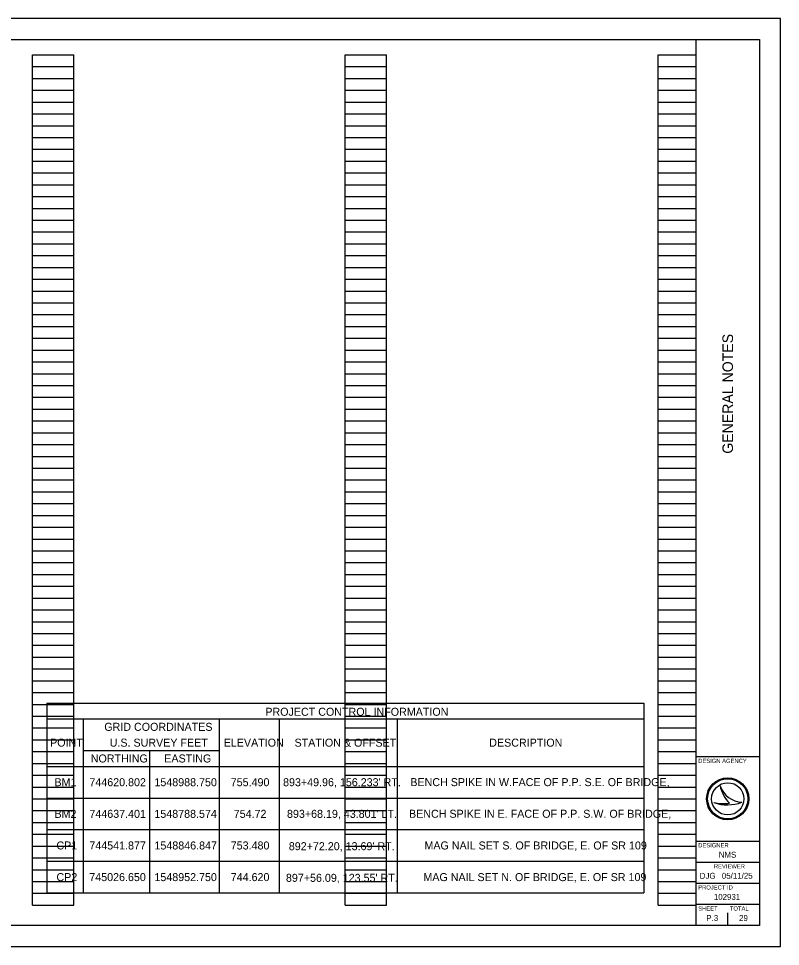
# Model space of a CAD drawing. Extents: x 0 to 34, y 0 to 22.
# Drawn here: x 15.93 to 34, y 0 to 22 of the extents above; entities that cross this region are included whole.
import ezdxf

# ---------------------------------------------------------------- set-up
doc = ezdxf.new("R2010")
doc.units = 0
for name, color, linetype in [('Default', 7, 'Continuous'), ('SH_Border', 7, 'Continuous'), ('SH_Cut_Line', 7, 'Continuous'), ('SH_Data', 7, 'Continuous'), ('SH_Text', 7, 'Continuous')]:
    doc.layers.add(name, color=color, linetype=linetype)

msp = doc.modelspace()

# ---------------------------------------------------------------- linework, layer by layer
at = {"layer": 'Default'}
for p, q in [((16.602, 5.769), (30.758, 5.769)), ((16.602, 5.769), (16.602, 1.269)), ((30.758, 5.769), (30.758, 1.269)), ((16.602, 5.394), (30.758, 5.394)), ((17.464, 5.394), (17.464, 1.269)), ((20.689, 5.394), (20.689, 1.269)), ((22.114, 5.394), (22.114, 1.269)), ((24.908, 5.394), (24.908, 1.269)), ((17.464, 4.644), (20.689, 4.644)), ((19.039, 4.644), (19.039, 1.269)), ((16.602, 4.269), (30.758, 4.269)), ((16.602, 3.519), (30.758, 3.519)), ((16.602, 2.769), (30.758, 2.769)), ((16.602, 2.019), (30.758, 2.019)), ((16.602, 1.269), (30.758, 1.269)), ((16.602, 1.269), (30.758, 1.269))]:
    msp.add_line(p, q, dxfattribs=at)
at = {"layer": 'SH_Border'}
for p, q in [((32, 0.5), (32, 21.5)), ((32, 4.5), (33.5, 4.5)), ((32, 2.5), (33.5, 2.5)), ((32, 2), (33.5, 2)), ((32, 1.5), (33.5, 1.5)), ((32, 1), (33.5, 1))]:
    msp.add_line(p, q, dxfattribs=at)
msp.add_lwpolyline([(1.5, 21.5), (33.5, 21.5), (33.5, 0.5), (1.5, 0.5)], close=True, dxfattribs=at)
at = {"layer": 'SH_Cut_Line'}
msp.add_lwpolyline([(0, 0), (34, 0), (34, 22), (0, 22)], close=True, dxfattribs=at)
at = {"layer": 'SH_Data'}
for p, q in [((16.26, 0.98), (16.26, 21.14)), ((16.26, 21.14), (17.24, 21.14)), ((17.24, 0.98), (17.24, 21.14)), ((23.68, 0.98), (23.68, 21.14)), ((23.68, 21.14), (24.66, 21.14)), ((24.66, 0.98), (24.66, 21.14)), ((31.1, 0.98), (31.1, 21.14)), ((31.1, 21.14), (32, 21.14)), ((32, 0.98), (32, 21.14)), ((16.26, 20.86), (17.24, 20.86)), ((23.68, 20.86), (24.66, 20.86)), ((31.1, 20.86), (32, 20.86)), ((16.26, 20.58), (17.24, 20.58)), ((23.68, 20.58), (24.66, 20.58)), ((31.1, 20.58), (32, 20.58)), ((16.26, 20.3), (17.24, 20.3)), ((23.68, 20.3), (24.66, 20.3)), ((31.1, 20.3), (32, 20.3)), ((16.26, 20.02), (17.24, 20.02)), ((23.68, 20.02), (24.66, 20.02)), ((31.1, 20.02), (32, 20.02)), ((16.26, 19.74), (17.24, 19.74)), ((23.68, 19.74), (24.66, 19.74)), ((31.1, 19.74), (32, 19.74)), ((16.26, 19.46), (17.24, 19.46)), ((23.68, 19.46), (24.66, 19.46)), ((31.1, 19.46), (32, 19.46)), ((16.26, 19.18), (17.24, 19.18)), ((23.68, 19.18), (24.66, 19.18)), ((31.1, 19.18), (32, 19.18)), ((16.26, 18.9), (17.24, 18.9)), ((23.68, 18.9), (24.66, 18.9)), ((31.1, 18.9), (32, 18.9)), ((16.26, 18.62), (17.24, 18.62)), ((23.68, 18.62), (24.66, 18.62)), ((31.1, 18.62), (32, 18.62)), ((16.26, 18.34), (17.24, 18.34)), ((23.68, 18.34), (24.66, 18.34)), ((31.1, 18.34), (32, 18.34)), ((16.26, 18.06), (17.24, 18.06)), ((23.68, 18.06), (24.66, 18.06)), ((31.1, 18.06), (32, 18.06)), ((16.26, 17.78), (17.24, 17.78)), ((23.68, 17.78), (24.66, 17.78)), ((31.1, 17.78), (32, 17.78)), ((16.26, 17.5), (17.24, 17.5)), ((23.68, 17.5), (24.66, 17.5)), ((31.1, 17.5), (32, 17.5)), ((16.26, 17.22), (17.24, 17.22)), ((23.68, 17.22), (24.66, 17.22)), ((31.1, 17.22), (32, 17.22)), ((16.26, 16.94), (17.24, 16.94)), ((23.68, 16.94), (24.66, 16.94)), ((31.1, 16.94), (32, 16.94)), ((16.26, 16.66), (17.24, 16.66)), ((23.68, 16.66), (24.66, 16.66)), ((31.1, 16.66), (32, 16.66)), ((16.26, 16.38), (17.24, 16.38)), ((23.68, 16.38), (24.66, 16.38)), ((31.1, 16.38), (32, 16.38)), ((16.26, 16.1), (17.24, 16.1)), ((23.68, 16.1), (24.66, 16.1)), ((31.1, 16.1), (32, 16.1)), ((16.26, 15.82), (17.24, 15.82)), ((23.68, 15.82), (24.66, 15.82)), ((31.1, 15.82), (32, 15.82)), ((16.26, 15.54), (17.24, 15.54)), ((23.68, 15.54), (24.66, 15.54)), ((31.1, 15.54), (32, 15.54)), ((16.26, 15.26), (17.24, 15.26)), ((23.68, 15.26), (24.66, 15.26)), ((31.1, 15.26), (32, 15.26)), ((16.26, 14.98), (17.24, 14.98)), ((23.68, 14.98), (24.66, 14.98)), ((31.1, 14.98), (32, 14.98)), ((16.26, 14.7), (17.24, 14.7)), ((23.68, 14.7), (24.66, 14.7)), ((31.1, 14.7), (32, 14.7)), ((16.26, 14.42), (17.24, 14.42)), ((23.68, 14.42), (24.66, 14.42)), ((31.1, 14.42), (32, 14.42)), ((16.26, 14.14), (17.24, 14.14)), ((23.68, 14.14), (24.66, 14.14)), ((31.1, 14.14), (32, 14.14)), ((16.26, 13.86), (17.24, 13.86)), ((23.68, 13.86), (24.66, 13.86)), ((31.1, 13.86), (32, 13.86)), ((16.26, 13.58), (17.24, 13.58)), ((23.68, 13.58), (24.66, 13.58)), ((31.1, 13.58), (32, 13.58)), ((16.26, 13.3), (17.24, 13.3)), ((23.68, 13.3), (24.66, 13.3)), ((31.1, 13.3), (32, 13.3)), ((16.26, 13.02), (17.24, 13.02)), ((23.68, 13.02), (24.66, 13.02)), ((31.1, 13.02), (32, 13.02)), ((16.26, 12.74), (17.24, 12.74)), ((23.68, 12.74), (24.66, 12.74)), ((31.1, 12.74), (32, 12.74)), ((16.26, 12.46), (17.24, 12.46)), ((23.68, 12.46), (24.66, 12.46)), ((31.1, 12.46), (32, 12.46)), ((16.26, 12.18), (17.24, 12.18)), ((23.68, 12.18), (24.66, 12.18)), ((31.1, 12.18), (32, 12.18)), ((16.26, 11.9), (17.24, 11.9)), ((23.68, 11.9), (24.66, 11.9)), ((31.1, 11.9), (32, 11.9)), ((16.26, 11.62), (17.24, 11.62)), ((23.68, 11.62), (24.66, 11.62)), ((31.1, 11.62), (32, 11.62)), ((16.26, 11.34), (17.24, 11.34)), ((23.68, 11.34), (24.66, 11.34)), ((31.1, 11.34), (32, 11.34)), ((16.26, 11.06), (17.24, 11.06)), ((23.68, 11.06), (24.66, 11.06)), ((31.1, 11.06), (32, 11.06)), ((16.26, 10.78), (17.24, 10.78)), ((23.68, 10.78), (24.66, 10.78)), ((31.1, 10.78), (32, 10.78)), ((16.26, 10.5), (17.24, 10.5)), ((23.68, 10.5), (24.66, 10.5)), ((31.1, 10.5), (32, 10.5)), ((16.26, 10.22), (17.24, 10.22)), ((23.68, 10.22), (24.66, 10.22)), ((31.1, 10.22), (32, 10.22)), ((16.26, 9.94), (17.24, 9.94)), ((23.68, 9.94), (24.66, 9.94)), ((31.1, 9.94), (32, 9.94)), ((16.26, 9.66), (17.24, 9.66)), ((23.68, 9.66), (24.66, 9.66)), ((31.1, 9.66), (32, 9.66)), ((16.26, 9.38), (17.24, 9.38)), ((23.68, 9.38), (24.66, 9.38)), ((31.1, 9.38), (32, 9.38)), ((16.26, 9.1), (17.24, 9.1)), ((23.68, 9.1), (24.66, 9.1)), ((31.1, 9.1), (32, 9.1)), ((16.26, 8.82), (17.24, 8.82)), ((23.68, 8.82), (24.66, 8.82)), ((31.1, 8.82), (32, 8.82)), ((16.26, 8.54), (17.24, 8.54)), ((23.68, 8.54), (24.66, 8.54)), ((31.1, 8.54), (32, 8.54)), ((16.26, 8.26), (17.24, 8.26)), ((23.68, 8.26), (24.66, 8.26)), ((31.1, 8.26), (32, 8.26)), ((16.26, 7.98), (17.24, 7.98)), ((23.68, 7.98), (24.66, 7.98)), ((31.1, 7.98), (32, 7.98)), ((16.26, 7.7), (17.24, 7.7)), ((23.68, 7.7), (24.66, 7.7)), ((31.1, 7.7), (32, 7.7)), ((16.26, 7.42), (17.24, 7.42)), ((23.68, 7.42), (24.66, 7.42)), ((31.1, 7.42), (32, 7.42)), ((16.26, 7.14), (17.24, 7.14)), ((23.68, 7.14), (24.66, 7.14)), ((31.1, 7.14), (32, 7.14)), ((16.26, 6.86), (17.24, 6.86)), ((23.68, 6.86), (24.66, 6.86)), ((31.1, 6.86), (32, 6.86)), ((16.26, 6.58), (17.24, 6.58)), ((23.68, 6.58), (24.66, 6.58)), ((31.1, 6.58), (32, 6.58)), ((16.26, 6.3), (17.24, 6.3)), ((23.68, 6.3), (24.66, 6.3)), ((31.1, 6.3), (32, 6.3)), ((16.26, 6.02), (17.24, 6.02)), ((23.68, 6.02), (24.66, 6.02)), ((31.1, 6.02), (32, 6.02)), ((16.26, 5.74), (17.24, 5.74)), ((23.68, 5.74), (24.66, 5.74)), ((31.1, 5.74), (32, 5.74)), ((16.26, 5.46), (17.24, 5.46)), ((23.68, 5.46), (24.66, 5.46)), ((31.1, 5.46), (32, 5.46)), ((16.26, 5.18), (17.24, 5.18)), ((23.68, 5.18), (24.66, 5.18)), ((31.1, 5.18), (32, 5.18)), ((16.26, 4.9), (17.24, 4.9)), ((23.68, 4.9), (24.66, 4.9)), ((31.1, 4.9), (32, 4.9)), ((16.26, 4.62), (17.24, 4.62)), ((23.68, 4.62), (24.66, 4.62)), ((31.1, 4.62), (32, 4.62)), ((16.26, 4.34), (17.24, 4.34)), ((23.68, 4.34), (24.66, 4.34)), ((31.1, 4.34), (32, 4.34)), ((16.26, 4.06), (17.24, 4.06)), ((23.68, 4.06), (24.66, 4.06)), ((31.1, 4.06), (32, 4.06)), ((16.26, 3.78), (17.24, 3.78)), ((23.68, 3.78), (24.66, 3.78)), ((31.1, 3.78), (32, 3.78)), ((32.567, 3.81), (32.567, 3.81)), ((16.26, 3.5), (17.24, 3.5)), ((23.68, 3.5), (24.66, 3.5)), ((31.1, 3.5), (32, 3.5)), ((32.417, 3.41), (32.417, 3.41)), ((32.75, 3.5), (32.75, 3.5)), ((33.087, 3.419), (33.087, 3.419)), ((16.26, 3.22), (17.24, 3.22)), ((23.68, 3.22), (24.66, 3.22)), ((31.1, 3.22), (32, 3.22)), ((16.26, 2.94), (17.24, 2.94)), ((23.68, 2.94), (24.66, 2.94)), ((31.1, 2.94), (32, 2.94)), ((16.26, 2.66), (17.24, 2.66)), ((23.68, 2.66), (24.66, 2.66)), ((31.1, 2.66), (32, 2.66)), ((16.26, 2.38), (17.24, 2.38)), ((23.68, 2.38), (24.66, 2.38)), ((31.1, 2.38), (32, 2.38)), ((16.26, 2.1), (17.24, 2.1)), ((23.68, 2.1), (24.66, 2.1)), ((31.1, 2.1), (32, 2.1)), ((16.26, 1.82), (17.24, 1.82)), ((23.68, 1.82), (24.66, 1.82)), ((31.1, 1.82), (32, 1.82)), ((16.26, 1.54), (17.24, 1.54)), ((23.68, 1.54), (24.66, 1.54)), ((31.1, 1.54), (32, 1.54)), ((16.26, 1.26), (17.24, 1.26)), ((23.68, 1.26), (24.66, 1.26)), ((31.1, 1.26), (32, 1.26)), ((16.26, 0.98), (17.24, 0.98)), ((23.68, 0.98), (24.66, 0.98)), ((31.1, 0.98), (32, 0.98)), ((32.375, 0.675), (32.375, 0.675)), ((32.75, 0.5), (32.75, 0.8))]:
    msp.add_line(p, q, dxfattribs=at)
for radius in [0.5, 0.477, 0.477, 0.382]:
    msp.add_circle((32.75, 3.5), radius, dxfattribs=at)
for centre, radius, start, end in [((33.116, 3.998), 0.58, 198.9257, 198.9319), ((33.347, 3.97), 0.796, 191.6379, 191.6421), ((33.116, 3.998), 0.58, 198.9319, 267.1657), ((33.347, 3.97), 0.796, 191.6421, 226.0947), ((32.739, 4.37), 1.013, 251.4576, 290.0832), ((32.648, 4.654), 1.266, 259.4964, 259.4995), ((32.739, 4.37), 1.013, 251.4527, 251.4576), ((32.648, 4.654), 1.266, 259.4995, 276.6672)]:
    msp.add_arc(centre, radius, start, end, dxfattribs=at)

# ---------------------------------------------------------------- texts
at = {"layer": 'Default'}
for s, height, p in [('PROJECT CONTROL INFORMATION', 0.18975, (21.784, 5.469)), ('GRID COORDINATES', 0.18975, (17.965, 5.112)), ('POINT', 0.1898, (16.68, 4.737)), ('U.S. SURVEY FEET', 0.18975, (18.093, 4.737)), ('ELEVATION', 0.1898, (20.797, 4.737)), ('STATION & OFFSET', 0.18975, (22.477, 4.737)), ('DESCRIPTION', 0.18975, (27.094, 4.737)), ('NORTHING', 0.1898, (17.644, 4.362)), ('EASTING', 0.1898, (19.388, 4.362)), ('BM1', 0.1898, (16.784, 3.799)), ('BM2', 0.1898, (16.784, 3.049)), ('CP1', 0.1898, (16.831, 2.299)), ('CP2', 0.1898, (16.831, 1.549))]:
    msp.add_text(s, height=height, dxfattribs=at).set_placement(p)
at = {"layer": 'SH_Data'}
msp.add_text('GENERAL NOTES', height=0.25, rotation=90, dxfattribs=at).set_placement((32.875, 11.682))
for s, height, p in [('DESIGN AGENCY', 0.1, (32.05, 4.35)), ('DESIGNER', 0.1, (32.05, 2.35)), ('NMS', 0.14, (32.538, 2.105)), ('REVIEWER', 0.1, (32.422, 1.85)), ('DJG', 0.14, (32.087, 1.605)), ('05/11/25', 0.14, (32.611, 1.605)), ('PROJECT ID', 0.1, (32.05, 1.35)), ('102931', 0.14, (32.421, 1.105)), ('SHEET', 0.1, (32.05, 0.85)), ('TOTAL', 0.1, (32.8, 0.85)), ('P.3', 0.14, (32.241, 0.605)), ('29', 0.14, (33.019, 0.605))]:
    msp.add_text(s, height=height, dxfattribs=at).set_placement(p)
at = {"layer": 'SH_Text'}
for s, height, p in [('744620.802', 0.1898, (17.612, 3.799)), ('1548988.750', 0.18975, (19.154, 3.799)), ('755.490', 0.1898, (20.964, 3.799)), ("893+49.96, 156.233' RT.", 0.18975, (22.205, 3.799)), ('BENCH SPIKE IN W.FACE OF P.P. S.E. OF BRIDGE,', 0.18975, (25.223, 3.801)), ('744637.401', 0.1898, (17.612, 3.049)), ('1548788.574', 0.18975, (19.153, 3.049)), ('754.72', 0.1898, (21.035, 3.049)), ("893+68.19, 43.801' LT.", 0.18975, (22.298, 3.049)), ('BENCH SPIKE IN E. FACE OF P.P. S.W. OF BRIDGE,', 0.18975, (25.192, 3.051)), ('744541.877', 0.1898, (17.611, 2.299)), ('1548846.847', 0.18975, (19.155, 2.299)), ('753.480', 0.1898, (20.964, 2.299)), ("892+72.20, 13.69' RT.", 0.18975, (22.341, 2.282)), ('MAG NAIL SET S. OF BRIDGE, E. OF SR 109', 0.18975, (25.558, 2.299)), ('745026.650', 0.1898, (17.609, 1.549)), ('1548952.750', 0.18975, (19.154, 1.549)), ('744.620', 0.1898, (20.964, 1.549)), ("897+56.09, 123.55' RT.", 0.18975, (22.273, 1.532)), ('MAG NAIL SET N. OF BRIDGE, E. OF SR 109', 0.18975, (25.533, 1.549))]:
    msp.add_text(s, height=height, dxfattribs=at).set_placement(p)

doc.saveas('drawing.dxf')
